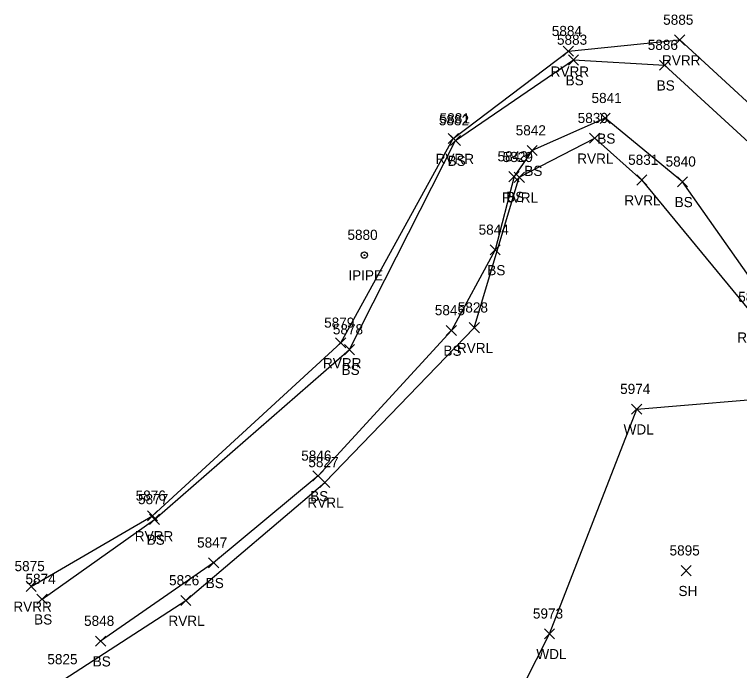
# Model space of a CAD drawing. Extents: x 1588028 to 1589597, y 137576 to 138176.
# Drawn here: x 1588431.3 to 1588574.1, y 138046.3 to 138175.6 of the extents above; entities that cross this region are included whole.
import ezdxf

# ---------------------------------------------------------------- set-up
doc = ezdxf.new("R2010")
doc.units = 0
for name, color, linetype in [('L_A', 7, 'Continuous'), ('L_I', 7, 'Continuous'), ('L_TIC', 7, 'Continuous'), ('LAWA', 7, 'Continuous'), ('LAWE', 7, 'Continuous'), ('LELB', 7, 'Continuous'), ('M_A', 7, 'Continuous'), ('M_I', 7, 'Continuous'), ('MPIP', 7, 'Continuous')]:
    doc.layers.add(name, color=color, linetype=linetype)

msp = doc.modelspace()

# ---------------------------------------------------------------- linework, layer by layer
at = {"layer": 'L_TIC'}
for points in [[(1588561.32, 138169.6), (1588563.32, 138171.6)], [(1588563.32, 138169.6), (1588561.32, 138171.6)], [(1588539.38, 138167.38), (1588541.38, 138169.38)], [(1588541.38, 138167.38), (1588539.38, 138169.38)], [(1588540.4, 138165.66), (1588542.4, 138167.66)], [(1588542.4, 138165.66), (1588540.4, 138167.66)], [(1588558.34, 138164.64), (1588560.34, 138166.64)], [(1588560.34, 138164.64), (1588558.34, 138166.64)], [(1588546.64, 138154.17), (1588548.64, 138156.17)], [(1588548.64, 138154.17), (1588546.64, 138156.17)], [(1588516.72, 138150.17), (1588518.72, 138152.17)], [(1588518.72, 138150.17), (1588516.72, 138152.17)], [(1588517.14, 138149.78), (1588519.14, 138151.78)], [(1588519.14, 138149.78), (1588517.14, 138151.78)], [(1588544.57, 138150.23), (1588546.57, 138152.23)], [(1588546.57, 138150.23), (1588544.57, 138152.23)], [(1588532.27, 138147.8), (1588534.27, 138149.8)], [(1588534.27, 138147.8), (1588532.27, 138149.8)], [(1588528.69, 138142.67), (1588530.69, 138144.67)], [(1588530.69, 138142.67), (1588528.69, 138144.67)], [(1588529.72, 138142.54), (1588531.72, 138144.54)], [(1588531.72, 138142.54), (1588529.72, 138144.54)], [(1588553.85, 138141.99), (1588555.85, 138143.99)], [(1588555.85, 138141.99), (1588553.85, 138143.99)], [(1588561.88, 138141.65), (1588563.88, 138143.65)], [(1588563.88, 138141.65), (1588561.88, 138143.65)], [(1588524.97, 138128.22), (1588526.97, 138130.22)], [(1588526.97, 138128.22), (1588524.97, 138130.22)], [(1588516.34, 138112.35), (1588518.34, 138114.35)], [(1588518.34, 138112.35), (1588516.34, 138114.35)], [(1588520.86, 138112.88), (1588522.86, 138114.88)], [(1588522.86, 138112.88), (1588520.86, 138114.88)], [(1588494.54, 138109.89), (1588496.54, 138111.89)], [(1588496.54, 138109.89), (1588494.54, 138111.89)], [(1588496.26, 138108.57), (1588498.26, 138110.57)], [(1588498.26, 138108.57), (1588496.26, 138110.57)], [(1588552.84, 138096.83), (1588554.84, 138098.83)], [(1588554.84, 138096.83), (1588552.84, 138098.83)], [(1588490.08, 138083.67), (1588492.08, 138085.67)], [(1588492.08, 138083.67), (1588490.08, 138085.67)], [(1588491.43, 138082.39), (1588493.43, 138084.39)], [(1588493.43, 138082.39), (1588491.43, 138084.39)], [(1588457.47, 138075.79), (1588459.47, 138077.79)], [(1588459.47, 138075.79), (1588457.47, 138077.79)], [(1588457.88, 138075.1), (1588459.88, 138077.1)], [(1588459.88, 138075.1), (1588457.88, 138077.1)], [(1588469.51, 138066.55), (1588471.51, 138068.55)], [(1588471.51, 138066.55), (1588469.51, 138068.55)], [(1588562.58, 138064.99), (1588564.58, 138066.99)], [(1588564.58, 138064.99), (1588562.58, 138066.99)], [(1588433.56, 138061.89), (1588435.56, 138063.89)], [(1588435.56, 138061.89), (1588433.56, 138063.89)], [(1588435.71, 138059.38), (1588437.71, 138061.38)], [(1588437.71, 138059.38), (1588435.71, 138061.38)], [(1588464.05, 138059.11), (1588466.05, 138061.11)], [(1588466.05, 138059.11), (1588464.05, 138061.11)], [(1588535.66, 138052.55), (1588537.66, 138054.55)], [(1588537.66, 138052.55), (1588535.66, 138054.55)], [(1588447.25, 138051.11), (1588449.25, 138053.11)], [(1588449.25, 138051.11), (1588447.25, 138053.11)]]:
    msp.add_lwpolyline(points, dxfattribs=at)
at = {"layer": 'LAWA'}
msp.add_lwpolyline([(1588438.89, 138034.8), (1588460.15, 138038.23), (1588480.55, 138035.11), (1588505.29, 138026.54), (1588523.98, 138028.49), (1588536.66, 138053.55), (1588553.84, 138097.83), (1588585.17, 138100.47), (1588614.56, 138103.49), (1588645.11, 138105.26), (1588662.06, 138103.96), (1588684.62, 138095.19), (1588717.93, 138069.71), (1588741.65, 138047.62), (1588762.05, 138028.09), (1588788.28, 138004.54)], dxfattribs=at)
at = {"layer": 'LAWE'}
for points in [[(1588434.56, 138062.89), (1588458.47, 138076.79), (1588495.54, 138110.89), (1588517.72, 138151.17), (1588540.38, 138168.38), (1588562.32, 138170.6), (1588586.16, 138148.71), (1588635.49, 138130.01), (1588676.05, 138127.99), (1588706.09, 138118.66), (1588727.82, 138096.85), (1588770.39, 138065.1), (1588798.8, 138043.18), (1588827.56, 138018.04), (1588869.93, 137975.12), (1588899.99, 137936.94), (1588912.08, 137921.5), (1588926.82, 137898.29), (1588932.86, 137884.09), (1588938.83, 137878.76)], [(1588441.02, 138044.54), (1588465.05, 138060.11), (1588492.43, 138083.39), (1588521.86, 138113.88), (1588530.72, 138143.54), (1588545.57, 138151.23), (1588554.85, 138142.99), (1588577.1, 138115.96), (1588614.25, 138110.98), (1588643.88, 138111.05), (1588664.41, 138106.89), (1588688.53, 138102.18), (1588718.75, 138082.48), (1588743.28, 138056.23), (1588764.53, 138038.44), (1588797.04, 138013.98), (1588814.47, 138001.04), (1588852.47, 137959.37), (1588883.95, 137928.09), (1588897.47, 137912.79), (1588913.44, 137894.45), (1588920.69, 137884.16), (1588921.99, 137878.45)]]:
    msp.add_lwpolyline(points, dxfattribs=at)
at = {"layer": 'LELB'}
for points in [[(1588436.71, 138060.38), (1588458.88, 138076.1), (1588497.26, 138109.57), (1588518.14, 138150.78), (1588541.4, 138166.66), (1588559.34, 138165.64), (1588582.3, 138144.56), (1588633.94, 138128.56), (1588675.55, 138127.05)], [(1588665.44, 138111.2), (1588642.17, 138115.15), (1588609.54, 138117.07), (1588578.85, 138119.94), (1588562.88, 138142.65), (1588547.64, 138155.17), (1588533.27, 138148.8), (1588529.69, 138143.67), (1588525.97, 138129.22), (1588517.34, 138113.35), (1588491.08, 138084.67), (1588470.51, 138067.55), (1588448.25, 138052.11)]]:
    msp.add_lwpolyline(points, dxfattribs=at)
at = {"layer": 'MPIP'}
for radius in [0.625, 0.0833]:
    msp.add_circle((1588500.21, 138128.2), radius, dxfattribs=at)

# ---------------------------------------------------------------- texts
at = {"layer": 'L_A'}
for s, p in [('RVRR', (1588558.83, 138165.6)), ('RVRR', (1588536.89, 138163.38)), ('BS', (1588539.84, 138161.66)), ('BS', (1588557.78, 138160.64)), ('BS', (1588546.08, 138150.17)), ('RVRR', (1588514.23, 138146.17)), ('RVRL', (1588542.13, 138146.23)), ('BS', (1588516.58, 138145.78)), ('BS', (1588531.71, 138143.8)), ('RVRL', (1588527.29, 138138.54)), ('BS', (1588528.14, 138138.67)), ('RVRL', (1588551.42, 138137.99)), ('BS', (1588561.32, 138137.65)), ('BS', (1588524.41, 138124.22)), ('RVRL', (1588573.66, 138110.96)), ('BS', (1588515.78, 138108.35)), ('RVRL', (1588518.43, 138108.88)), ('RVRR', (1588492.06, 138105.89)), ('BS', (1588495.7, 138104.57)), ('WDL', (1588551.26, 138092.83)), ('BS', (1588489.52, 138079.67)), ('RVRL', (1588488.99, 138078.39)), ('RVRR', (1588454.98, 138071.79)), ('BS', (1588457.32, 138071.1)), ('BS', (1588468.95, 138062.55)), ('SH', (1588562.07, 138060.99)), ('RVRR', (1588431.07, 138057.89)), ('BS', (1588435.15, 138055.38)), ('RVRL', (1588461.61, 138055.11)), ('WDL', (1588534.08, 138048.55)), ('BS', (1588446.69, 138047.11))]:
    msp.add_text(s, height=2, dxfattribs=at).set_placement(p)
at = {"layer": 'L_I'}
for s, p in [('5885', (1588559.06, 138173.6)), ('5884', (1588537.12, 138171.38)), ('5883', (1588538.14, 138169.66)), ('5886', (1588556.02, 138168.64)), ('5841', (1588544.95, 138158.17)), ('5882', (1588514.88, 138153.78)), ('5881', (1588515.03, 138154.17)), ('5830', (1588542.22, 138154.23)), ('5842', (1588530.01, 138151.8)), ('5843', (1588526.43, 138146.67)), ('5829', (1588527.45, 138146.54)), ('5831', (1588552.16, 138145.99)), ('5840', (1588559.54, 138145.65)), ('5844', (1588522.71, 138132.22)), ('5832', (1588573.84, 138118.96)), ('5845', (1588514.08, 138116.35)), ('5828', (1588518.6, 138116.88)), ('5879', (1588492.28, 138113.89)), ('5878', (1588494, 138112.57)), ('5974', (1588550.58, 138100.83)), ('5846', (1588487.77, 138087.67)), ('5827', (1588489.17, 138086.39)), ('5876', (1588455.15, 138079.79)), ('5877', (1588455.62, 138079.1)), ('5847', (1588467.25, 138070.55)), ('5895', (1588560.32, 138068.99)), ('5875', (1588431.3, 138065.89)), ('5874', (1588433.45, 138063.38)), ('5826', (1588461.73, 138063.11)), ('5973', (1588533.4, 138056.55)), ('5848', (1588444.99, 138055.11)), ('5825', (1588437.76, 138047.54))]:
    msp.add_text(s, height=2, dxfattribs=at).set_placement(p)
at = {"layer": 'M_A'}
msp.add_text('IPIPE', height=2, dxfattribs=at).set_placement((1588497.05, 138123.2))
at = {"layer": 'M_I'}
msp.add_text('5880', height=2, dxfattribs=at).set_placement((1588496.87, 138131.2))

doc.saveas('drawing.dxf')
